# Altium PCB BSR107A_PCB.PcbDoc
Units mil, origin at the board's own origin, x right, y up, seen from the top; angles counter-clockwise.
Board outline 2500 x 2500 mil, 4 copper layers (Top Layer, Signal Layer 1, Signal Layer 2, Bottom Layer), stack 64.4 mil thick; 58 components, 15 nets, 89 pads, 265 vias.
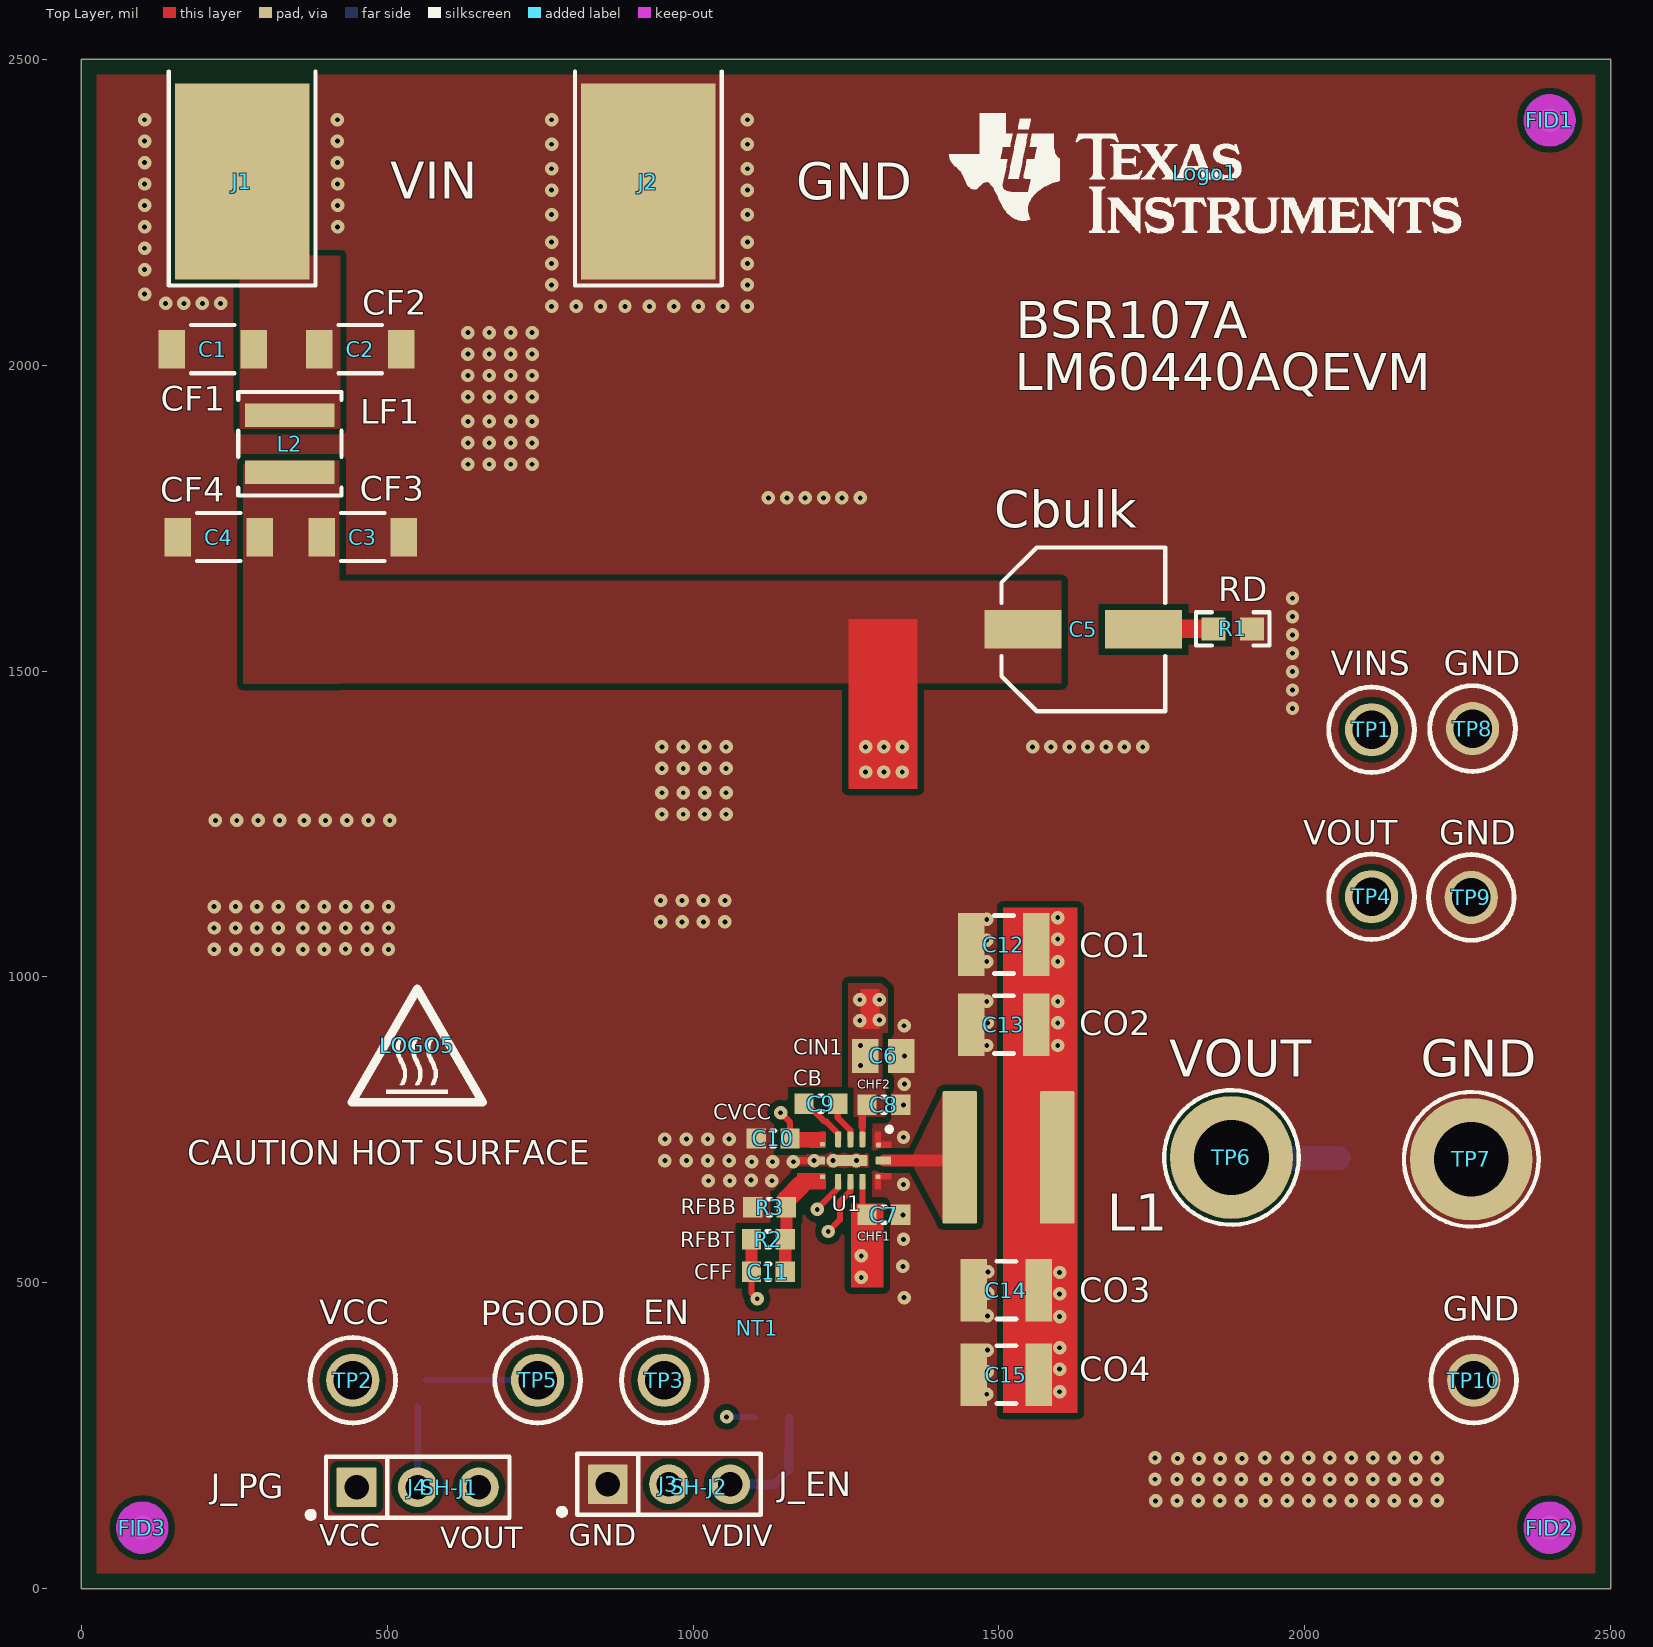
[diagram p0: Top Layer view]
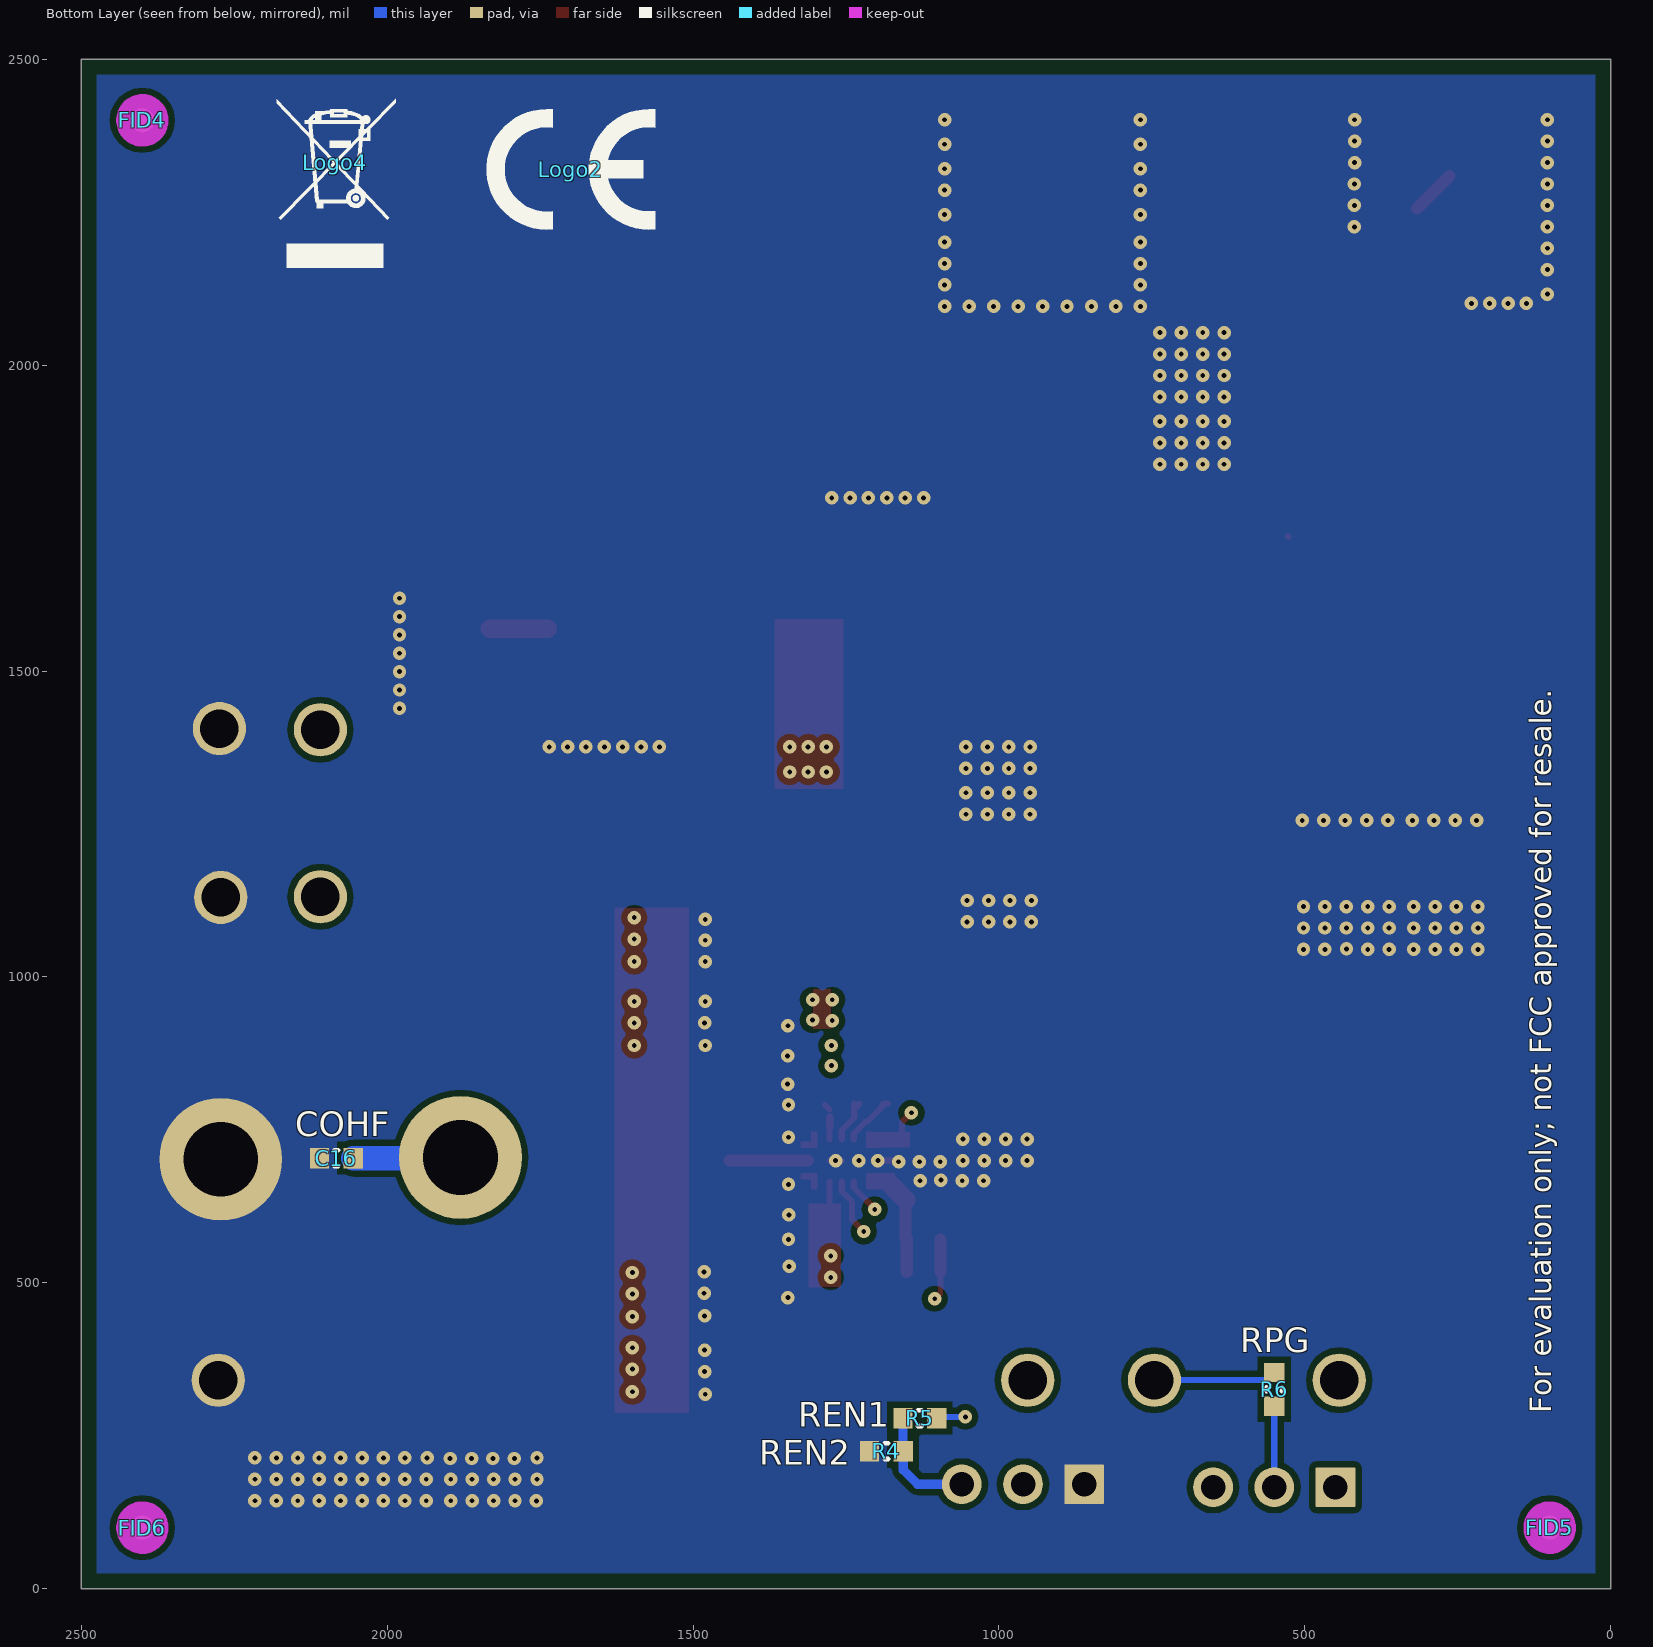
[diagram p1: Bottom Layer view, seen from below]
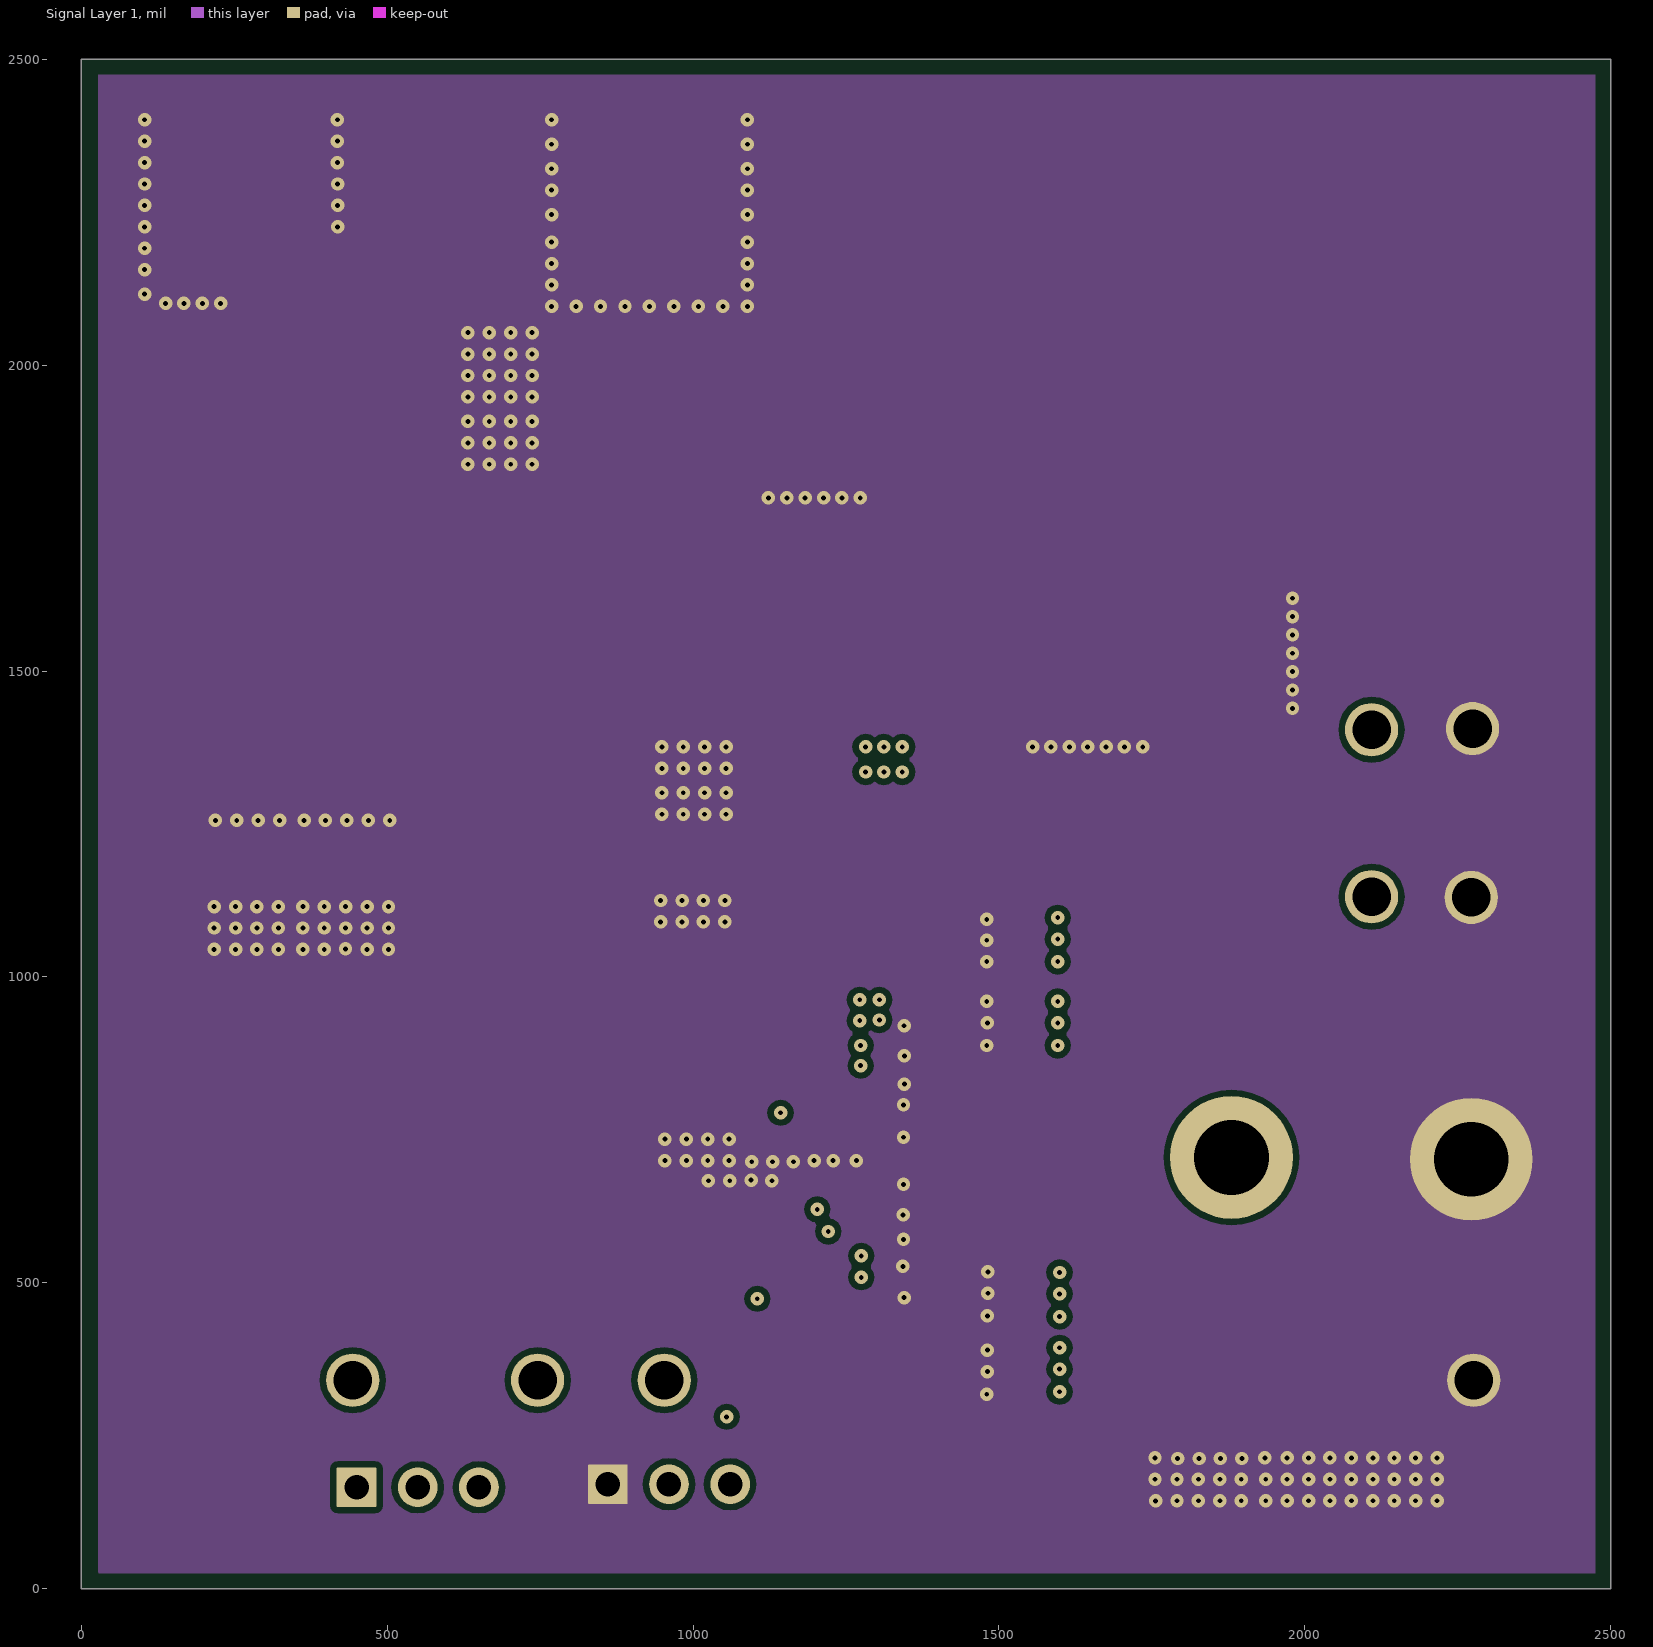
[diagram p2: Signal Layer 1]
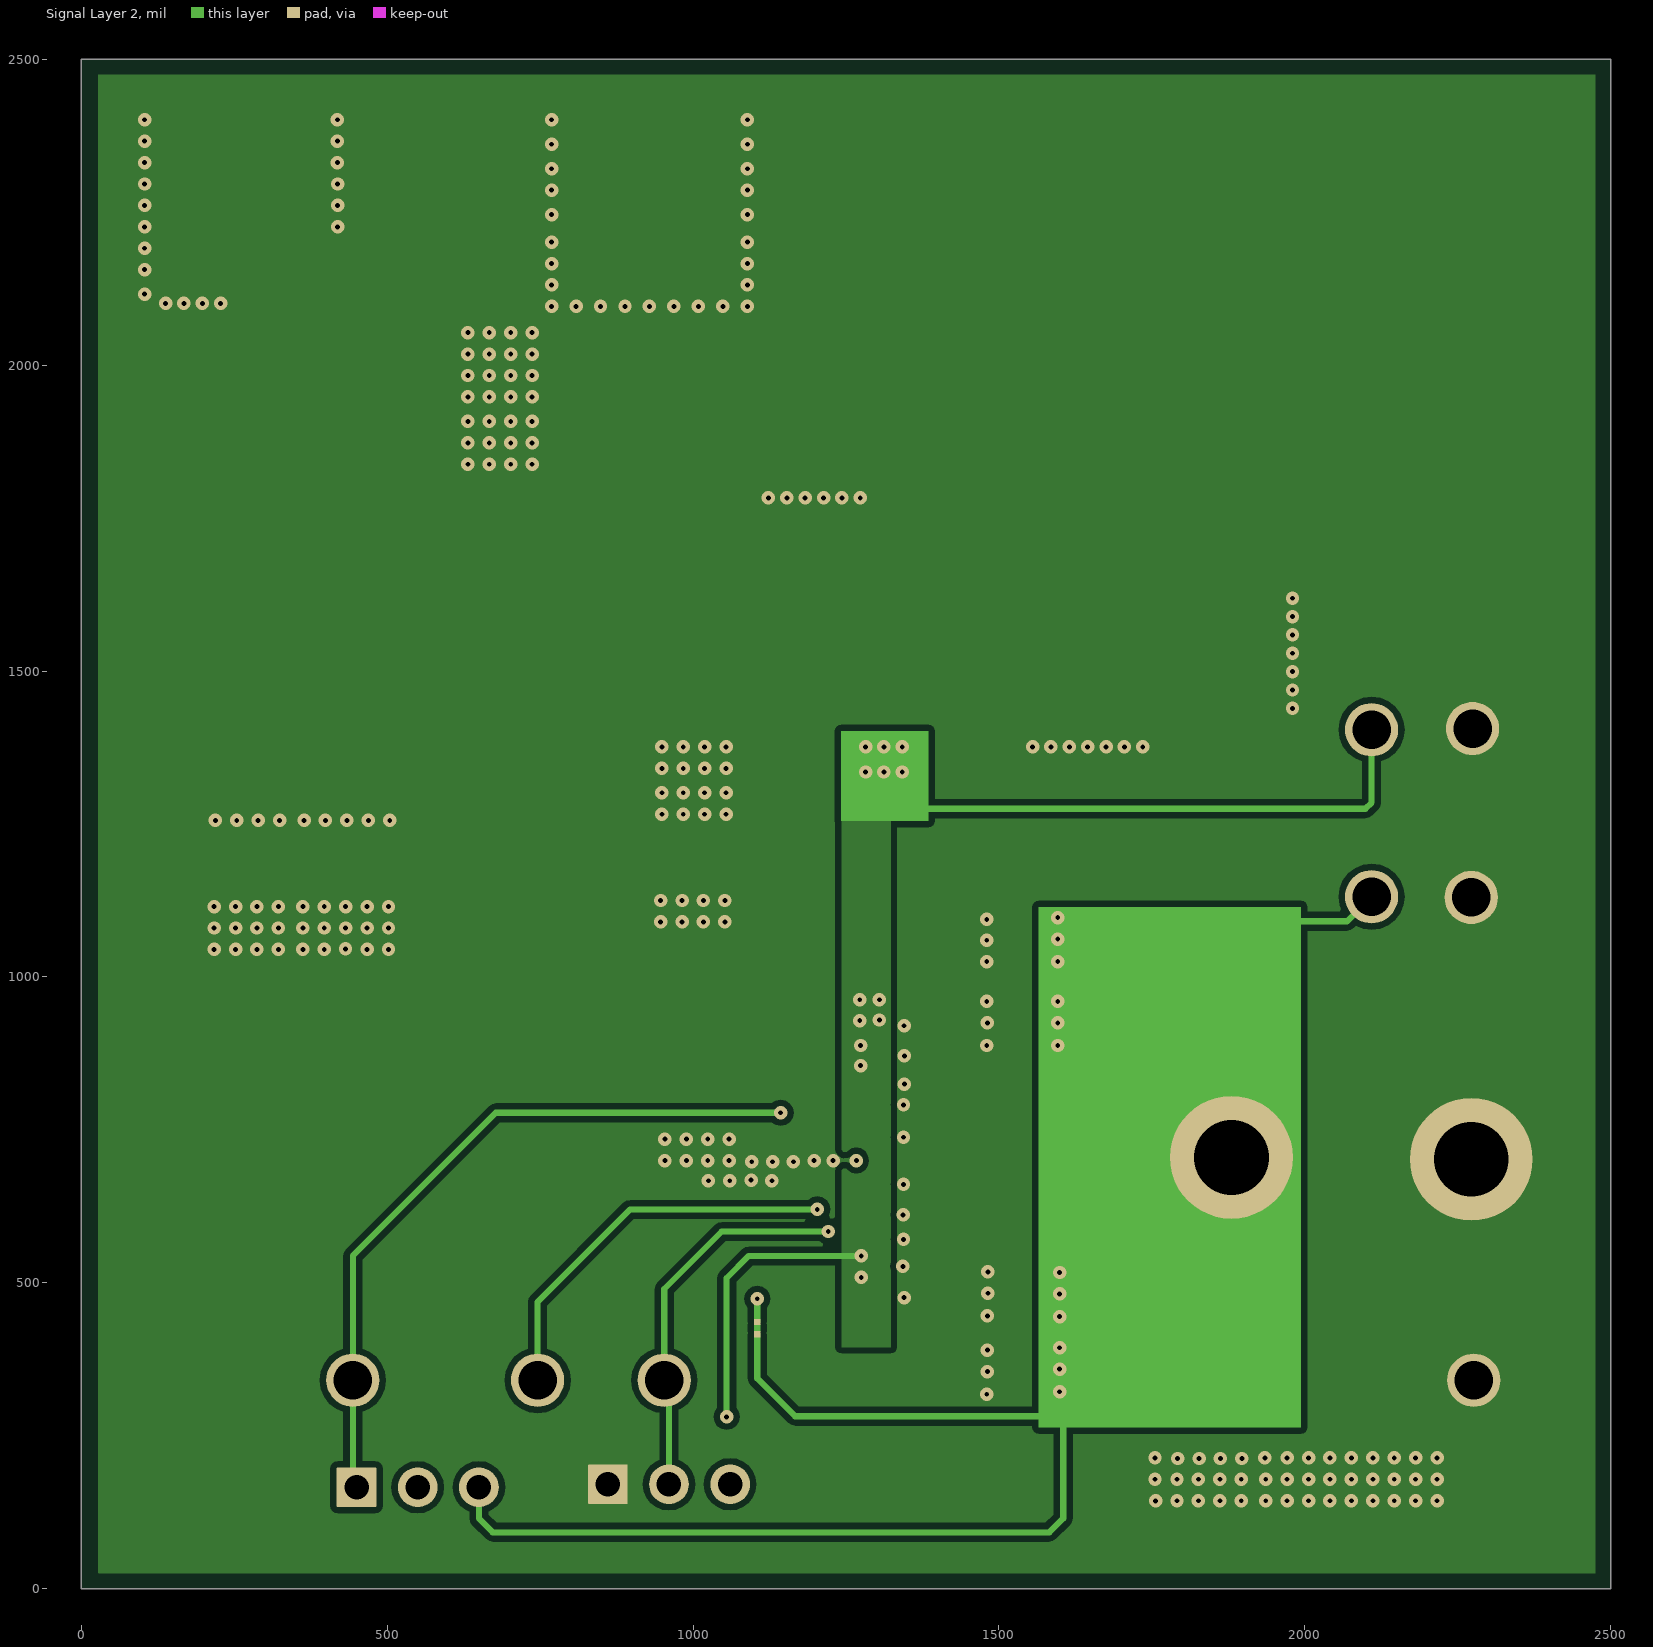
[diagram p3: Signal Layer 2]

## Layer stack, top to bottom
Top Solder: solder mask 0.4, Solder Resist, Dk 3.5
Top Layer: signal copper 2.8
Dielectric 3: core 14, FR-4 High TG, Dk 4.2
Signal Layer 1: signal copper 1.4
Dielectric 2: core 28, FR-4 High TG, Dk 4.2
Signal Layer 2: signal copper 1.4
Dielectric1: core 14, FR-4 HIgh TG, Dk 4.2
Bottom Layer: signal copper 2.8
Bottom Solder: solder mask 0.4, Solder Resist, Dk 3.5

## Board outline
0,0 0,2500 2500,2500 2500,0

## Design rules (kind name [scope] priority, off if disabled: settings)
AcuteAngle [All] p1: minimum=4.50000000000000E+0001 checktracksonly=FALSE
AssemblyTestPointUsage [All] p1: valid=2
BoardOutlineClearance BoardOutlineClearance_MountingHoles [OnCopper and InComponentClass('Mounting Holes')] p1: gap=40 ignorepadtopadclearanceinfootprint=FALSE
BoardOutlineClearance BoardOutlineClearance_Poly [OnCopper and IsPoly] p2: gap=25 ignorepadtopadclearanceinfootprint=FALSE
BoardOutlineClearance [OnCopper and Not InComponentClass('Logo') and not InComponentClass('FiducialMark') and not InRegion(1000,500,4000,800) and not InPoly] p3: gap=40 ignorepadtopadclearanceinfootprint=FALSE
Clearance Clearance_Keepouts [((IsTrack Or IsArc) And Not InPoly) And IsFree and IsKeepOut vs ((IsTrack Or IsArc) And Not InPoly) And IsFree and IsKeepOut] p1: gap=0 ignorepadtopadclearanceinfootprint=FALSE
Clearance Clearance_Poly [InPolygon] p2: gap=10 ignorepadtopadclearanceinfootprint=FALSE except(0: Arc-Hole Track-Hole SMDPad-Hole THPad-Hole Via-Hole Fill-Hole Poly-Hole Region-Hole Text-Hole)
Clearance Clearance_FiducialMark [IsKeepOut and InComponentClass('FiducialMark') vs IsPad and InComponentClass('FiducialMark')] p3: gap=0 ignorepadtopadclearanceinfootprint=FALSE
Clearance [All] p4: gap=7.79 ignorepadtopadclearanceinfootprint=FALSE
ComponentClearance ComponentClearance_MountingHoles_FiducialMarks [InComponentClass('Mounting Holes') vs InComponentClass('FiducialMark')] p1: gap=50 collisioncheckmode=3 verticalgap=10 showdistances=FALSE
ComponentClearance ComponentClearance_Shunt [InComponentClass('Header') vs InComponentClass('Shunt')] p2: gap=0 collisioncheckmode=3 verticalgap=0 showdistances=FALSE
ComponentClearance ComponentClearance_Logo [InComponentClass('Logo')] p3: gap=50 collisioncheckmode=3 verticalgap=10 showdistances=FALSE
ComponentClearance ComponentClearance_ScrewToNut [(HasFootprint('NY PMS 440 0025 PH')) vs (HasFootprint('Keystone_1902C'))] p4: gap=5 collisioncheckmode=3 verticalgap=10 showdistances=FALSE
ComponentClearance ComponentClearance_MountingHoles [InComponentClass('Mounting Holes')] p5: gap=250 collisioncheckmode=3 verticalgap=100000 showdistances=FALSE
ComponentClearance ComponentClearance_SmallPassives [HasFootprint('0201*') or HasFootprint('0402*') or HasFootprint('0508') or HasFootprint('0603*') or HasFootprint('0612') or HasFootprint('0805*') or HasFootprint('0815*') or HasFootprint('0830*') or HasFootprint('1206*') or HasFootprint('1210*') or HasFootprint('1808*') or HasFootprint('1812*') or HasFootprint('1825*') or HasFootprint('2010*') or HasFootprint('2220*') or HasFootprint('2225*') or HasFootprint('2512*') or HasFootprint('2728*') or HasFootprint('3518*') vs HasFootprint('0201*') or HasFootprint('0402*') or HasFootprint('0508') or HasFootprint('0603*') or HasFootprint('0612') or HasFootprint('0805*') or HasFootprint('0815*') or HasFootprint('0830*') or HasFootprint('1206*') or HasFootprint('1210*') or HasFootprint('1808*') or HasFootprint('1812*') or HasFootprint('1825*') or HasFootprint('2010*') or HasFootprint('2220*') or HasFootprint('2225*') or HasFootprint('2512*') or HasFootprint('2728*') or HasFootprint('3518*')] p6: gap=14.96 collisioncheckmode=3 verticalgap=10 showdistances=FALSE
ComponentClearance ComponentClearance_THtoSMT [IsThruComponent vs IsSMTComponent] p7: gap=40 collisioncheckmode=3 verticalgap=30 showdistances=FALSE
ComponentClearance ComponentClearance_THtoTH [IsThruComponent vs IsThruComponent] p8: gap=30 collisioncheckmode=3 verticalgap=30 showdistances=FALSE
ComponentClearance [All] p9: gap=30 collisioncheckmode=3 verticalgap=10 showdistances=FALSE
DiffPairsRouting [All] p1: maxlimit=100 minlimit=10 mostfreqgap=10 toplayer_minwidth=15 toplayer_maxwidth=15 toplayer_prefwidth=15 midlayer1_minwidth=15 midlayer1_maxwidth=15 midlayer1_prefwidth=15 midlayer2_minwidth=15 midlayer2_maxwidth=15 midlayer2_prefwidth=15 bottomlayer_minwidth=15 bottomlayer_maxwidth=15 bottomlayer_prefwidth=15 maxuncoupledlength=1000
FabricationTestPointUsage TestPointUsage [All] p1: valid=2 allowmultiple=FALSE
FabricationTestpoint Testpoint [All] p1: side=3 testpointundercomponent=TRUE minsize=40 maxsize=100 preferedsize=60 minholesize=0 maxholesize=40 preferedholesize=32 testpointgrid=1 allowsidetop=TRUE allowsidebottom=TRUE usegrid=TRUE gridtolerance=0.01
FanoutControl Fanout_LCC [IsLCC] p1: bgadir=Out bgaviamode=Centered fanoutstyle=Auto fanoutdirection=Alternating viagrid=1 // Fanout_LCC (Default Rule)
FanoutControl Fanout_BGA [IsBGA] p2: bgadir=Out bgaviamode=Centered fanoutstyle=Auto fanoutdirection=Alternating viagrid=1 // Fanout_BGA (Default Rule)
FanoutControl Fanout_Default [All] p4: bgadir=Out bgaviamode=Centered fanoutstyle=Auto fanoutdirection=Alternating viagrid=1 // Fanout_Default (Default Rule)
FanoutControl Fanout_Small [(CompPinCount < 5)] p5: bgadir=Out bgaviamode=Centered fanoutstyle=Auto fanoutdirection=OutThenIn viagrid=1 // Fanout_Small (Default Rule)
HoleSize [All] p1: absolutevalues=TRUE maxlimit=251 minlimit=7.87 maxpercent=80.000 minpercent=20.000
MinimumAnnularRing MinimumAnnularRing_ThermalPadVias [IsVia and InAnyComponent] p1: minimumring=5.91
MinimumAnnularRing [All] p2: minimumring=5
MinimumSolderMaskSliver MinimumSolderMaskSliver_Logo [InComponentClass('Logo') vs InComponentClass('Logo')] p1: minsoldermaskwidth=0.7
MinimumSolderMaskSliver [All] p2: minsoldermaskwidth=3.94
PlaneConnect [All] p1: planeconnectstyle=Relief reliefexpansion=10 reliefentries=4 reliefconductorwidth=10 reliefairgap=10
PolygonConnect [All] p1: connectstyle=Direct reliefconductorwidth=10 reliefentries=4 polygonreliefangle="90 Angle" airgapwidth=10
RoutingVias ThermalPadVias [IsVia and InAnyComponent] p1: holewidth=7.87 width=19.68 viastyle="Through Hole" minholewidth=7.87 minwidth=19.68 maxholewidth=12.99 maxwidth=23.62
RoutingVias [All] p2: holewidth=16 width=34 viastyle="Through Hole" minholewidth=7.87 minwidth=18 maxholewidth=40 maxwidth=65
SilkToBoardRegionClearance [Not ((IsComment or IsDesignator) And (Hide <> 'False')) and not InRegion(1000,500,4000,800)] p1:
SilkToSilkClearance SilkToSilkClearance_Pb-FreeLogo [(HasFootprint('Pb-Free_Overlay_Medium') OR HasFootprint('Pb-Free_Overlay_Small')) vs (HasFootprint('Pb-Free_Overlay_Medium') OR HasFootprint('Pb-Free_Overlay_Small'))] p1: silktosilkclearance=0
SilkToSilkClearance [All] p2: silktosilkclearance=4
SilkToSolderMaskClearance SilkToComponentPadClearance [(IsPad or IsFill or IsRegion) and InAnycomponent] p1: minsilkscreentomaskgap=5 clearancetoexposedcopper=TRUE
SilkToSolderMaskClearance "Silk to Solder Mask Opening" [All] p2: minsilkscreentomaskgap=4 clearancetoexposedcopper=FALSE
SolderMaskExpansion [All] p1: expansion=1.97
Width [All] p1: maxlimit=100 minlimit=6 preferedwidth=10 checkconnectedcopper=TRUE
15 further rules are at their usual default settings.

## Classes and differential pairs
component class FiducialMark: FID1 FID2 FID3 FID4 FID5 FID6
component class Shunt: SH-J1 SH-J2
component class Header: J3 J4
component class BSR107A_EVM: 3 C1 C2 C3 C4 C5 C6 C7 C8 C9 C10 C11 C12 C13 C14 C15 C16 CB CHF2 CIN1 COUT1 GND GND4 GND5 J1 J2 J3 J4 L1 L2 NT1 R1 R2 R3 R4 R5 R6 TP1 TP2 TP3 TP4 TP5 TP6 TP7 TP8 TP9 TP10 U1 vin
component class AssemblyNote: ZZ2 ZZ3 ZZ4 ZZ5 ZZ6
component class BSR107A_EVM_Hardware: FID1 FID2 FID3 FID4 FID5 FID6 Logo1 Logo2 Logo3 Logo4 LOGO5 SH-J1 SH-J2 ZZ2 ZZ3 ZZ4 ZZ5 ZZ6
component class Logo: Logo1

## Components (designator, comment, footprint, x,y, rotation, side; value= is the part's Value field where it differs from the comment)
C1 "CF1" 1206_180 215,2026 r180 top value=4.7uF
C2 "CF2" 1206_180 456,2026 r0 top value=4.7uF
C3 "CF3" 1206_180 460,1719 r0 top value=4.7uF
C4 "CF4" 1206_180 225,1719 r180 top value=4.7uF
C5 "Cbulk" SM_RADIAL_D 1638,1568 r0 top value=22uF
C6 "CIN1" 0805L 1311,871 r0 top value=4.7uF
C7 "CHF1" 0603L 1312,611 r0 top value=0.22uF
C8 "CHF2" 0603L 1312,791 r0 top value=0.22uF
C9 "CB" 0603L 1209,793 r180 top value=0.1uF
C10 "CVCC" 0603L 1131,736 r180 top value=1uF
C11 "CFF" 0603L 1123,518 r0 top value=22pF
C12 "CO1" 1210L 1508,1053 r180 top value=22uF
C13 "CO2" 1210_270L 1508,922 r180 top value=47uF
C14 "CO3" 1210_270L 1512,488 r180 top value=47uF
C15 "CO4" 1210L 1512,350 r180 top value=22uF
C16 "COHF" 0603L 2083,704 r0 bottom value=0.1uF
FID1 "Fiducial" Fiducial10-20 2400,2400 r0 top
FID2 "Fiducial" Fiducial10-20 2400,100 r0 top
FID3 "Fiducial" Fiducial10-20 100,100 r0 top
FID4 "Fiducial" Fiducial10-20 2400,2400 r180 bottom
FID5 "Fiducial" Fiducial10-20 100,100 r180 bottom
FID6 "Fiducial" Fiducial10-20 2400,100 r180 bottom
J1 "VIN" 6091 263,2485 r270 top
J2 "GND" 6092 927,2485 r270 top
J3 "J_EN" Samtec_HTSW-103-07-G-S 960.67,170.89 r0 top
J4 "J_PG" Samtec_HTSW-103-07-G-S 550,166 r0 top
L1 "XAL6060-682MEB" XAL6060 1515.5,705 r0 top value=6.8uH
L2 "LF1" XAL4030 341,1871.5 r270 top value=3.3uH
Logo1 "Texas Instruments" TI_Stacked_Overlay_Small 1836.89,2313.76 r0 top
Logo2 "CE Mark" CE_Mark_5mm 1699.85,2319.94 r180 bottom
Logo3 "FCC disclaimer" FCC_disclaimer -478.56,846.5 r180 bottom
Logo4 "WEEE logo" WEEE_Minimum 2085.16,2331 r180 bottom
LOGO5 "CAUTION HOT SURFACE" IEC_HotSurface_Small 549,888 r0 top
NT1 "Net-Tie" Net-Tie_10mil 1105,426 r270 top net-tie
R1 "RD" 0603 1882,1569 r180 top value=0
R2 "RFBT" 0603L 1123,571 r180 top value=100k
R3 "RFBB" 0603L 1125,624 r0 top value=24.9k
R4 "REN2" 0603L 1184,225 r180 bottom value=10.0k
R5 "REN1" 0603L 1129.35,279 r180 bottom value=10.0k
R6 "RPG" 0603L 550,326 r90 bottom value=100k
SH-J1 "SNT-100-BK-G" SNT-100-BK-G 602,166 r180 top value=1x2
SH-J2 "SNT-100-BK-G" SNT-100-BK-G 1010,167 r180 top value=1x2
TP1 "VINS" Keystone5010 2109,1404 r0 top
TP2 "VCC" Keystone5014 444,341 r0 top
TP3 "EN" Keystone5014 953,341 r0 top
TP4 "VOUT" Keystone5010 2109,1131 r0 top
TP5 "PGOOD" Keystone5014 746,341 r0 top
TP6 "VOUT" Keystone1503-2 1880,705 r0 top
TP7 "GND" Keystone1503-2 2272,702 r0 top
TP8 "GND" Keystone5011 2274,1406 r0 top
TP9 "GND" Keystone5011 2272,1130 r0 top
TP10 "GND" Keystone5011 2276,341 r0 top
U1 "LM60440-Q1" RPK0013A 1257,700 r270 top
ZZ2 "These assemblies are ESD sensitive, ESD precautions shall be observed." AssemblyNote 52.27,3634.11 r0 top
ZZ3 "These assemblies must be clean and free from flux and all contaminants. Use of no clean flux is not acceptable." AssemblyNote 52.27,3545.56 r0 top
ZZ4 "These assemblies must comply with workmanship standards IPC-A-610 Class 2, unless otherwise specified." AssemblyNote 52.27,3457 r0 top
ZZ5 "Place shunt jumper (SH-J1) on jumper (J3) in position 2-3" AssemblyNote 50,3269.73 r0 top
ZZ6 "Place shunt jumper (SH-J2) on jumper (J4) in position 2-3" AssemblyNote 51,3362.73 r0 top

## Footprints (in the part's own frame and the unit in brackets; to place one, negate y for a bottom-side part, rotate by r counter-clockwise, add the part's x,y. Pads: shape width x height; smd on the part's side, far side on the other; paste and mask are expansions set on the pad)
0603 [mm] "0603 from SM-752 data"
  rect 1x0.95 smd: 1(-0.8,0) 2(0.8,0)
  silkscreen extent -1.52,-0.69 1.52,0.69, body extent -0.87,-0.47 0.87,0.47, height 1
0603L [mm] "0603 from SM-752 data"
  rect 0.8x0.85 smd: 1(-0.7,0) 2(0.7,0)
  silkscreen extent -0.07,-0.33 0.07,0.33, body extent -0.87,-0.47 0.87,0.47, height 1
0805L [mm] "0805 from SM-752 data"
  rect 1.1x1.4 smd: 1(-0.75,0) 2(0.75,0)
  body extent -1.1,-0.72 1.1,0.72, height 1.45
1206_180 [mm] "1206_180"
  rect 1.1x1.6 smd: 1(-1.7,0) 2(1.7,0)
  silkscreen extent -0.9,-1 0.9,1, body extent -1.75,-0.95 1.75,0.95, height 1.8
1210_270L [mm] "1210"
  rect 1.1x2.6 smd: 1(-1.35,0) 2(1.35,0)
  silkscreen extent -0.4,-1.2 0.4,1.2, body extent -1.7,-1.35 1.7,1.35, height 2.7
1210L [mm] "1210 from SM-752 data"
  rect 1.1x2.6 smd: 1(-1.35,0) 2(1.35,0)
  silkscreen extent -0.4,-1.2 0.4,1.2, body extent -1.7,-1.35 1.7,1.35, height 1.35
6091 [mil] "Keystone Insulated End Launch Banana Jack"
  rect 320x220 smd: 1(185,0)
  silkscreen extent 5,-120 355,120, body extent -666,-216 271,216, height 227
6092 [mil] "Keystone Insulated End Launch Banana Jack"
  rect 320x220 smd: 1(185,0)
  silkscreen extent 5,-120 355,120, body extent -666,-216 271,216, height 227
AssemblyNote [mil] "Assembly Note"
CE_Mark_5mm [mil] "Minimum text height for CE Mark"
  silkscreen extent -138,-98 138,98
FCC_disclaimer [mil]
Fiducial10-20 [mm]
  round 1 smd mask+0.5: 1(0,0)
  Top Layer keep-out circle w1.178: c0,0 r0.5
IEC_HotSurface_Small [mil]
  silkscreen extent -107,-93 107,92
Keystone1503-2 [mm] "Double Turret"
  round 5.1 hole 3.1: 1(0,0)
  silkscreen extent -2.79,-2.79 2.79,2.79, body extent -2.4,-2.4 2.38,2.4, height 9.22
Keystone5010 [mil] "Keystone Multipurpose loops"
  round 87 hole 63: 1(0,0)
  silkscreen extent -70,-70 70,70, body extent -63,-63 63,62, height 319
Keystone5011 [mil] "Keystone Multipurpose loops"
  round 87 hole 63: 1(0,0)
  silkscreen extent -70,-70 70,70, body extent -63,-63 63,62, height 319
Keystone5014 [mil] "Keystone Multipurpose loops"
  round 87 hole 63: 1(0,0)
  silkscreen extent -70,-70 70,70, body extent -63,-63 63,62, height 319
Net-Tie_10mil [mil] "10mil net tie, no solder mask opening, no solder paste"
  rect 10x10 on Mid2 paste-5 mask-5: 1(-10,0) 2(10,0)
  Signal Layer 2 region: -6,5 6,5 6,-5 -6,-5
RPK0013A [mm] "QFN, 13-Leads, Body 2x3mm, Ptich 0.5mm"
  rrect50% 0.2x0.2 smd: 1(-0.65,1.175) 5(-0.675,-1.15) 7(0.675,-1.15) 11(0.675,1.15)
  rrect40% 0.65x0.25 smd: 2(-0.875,0.5) 3(-0.875,0) 4(-0.875,-0.5) 8(0.875,-0.5) 9(0.875,0) 10(0.875,0.5)
  rrect29% 0.35x0.65 smd: 6(0,-1.375) 12(0,1.375)
  rrect22% 0.45x1.45 smd: 13(0,0)
  Top Layer region: -1.2,1.075 -1.2,1.225 -1.196,1.244 -1.185,1.26 -1.169,1.271 -1.15,1.275 -1.15,1.275 -0.825,1.275 -0.806,1.279 -0.79,1.29 -0.779,1.306 -0.775,1.325 -0.775,1.325 -0.775,1.65 -0.771,1.669 -0.76,1.685 -0.744,1.696 -0.725,1.7 -0.725,1.7 -0.575,1.7 -0.556,1.696 -0.54,1.685 -0.529,1.669 -0.525,1.65 -0.525,1.65 -0.525,1.075 -0.529,1.056 -0.54,1.04 -0.556,1.029 -0.575,1.025 -0.575,1.025 -1.15,1.025 -1.169,1.029 -1.185,1.04 -1.196,1.056 -1.2,1.075
  Top Layer region: 1.2,1.075 1.2,1.225 1.196,1.244 1.185,1.26 1.169,1.271 1.15,1.275 1.15,1.275 0.825,1.275 0.806,1.279 0.79,1.29 0.779,1.306 0.775,1.325 0.775,1.325 0.775,1.65 0.771,1.669 0.76,1.685 0.744,1.696 0.725,1.7 0.725,1.7 0.575,1.7 0.556,1.696 0.54,1.685 0.529,1.669 0.525,1.65 0.525,1.65 0.525,1.075 0.529,1.056 0.54,1.04 0.556,1.029 0.575,1.025 0.575,1.025 1.15,1.025 1.169,1.029 1.185,1.04 1.196,1.056 1.2,1.075
  Top Layer region: 0.575,-1.7 0.725,-1.7 0.744,-1.696 0.76,-1.685 0.771,-1.669 0.775,-1.65 0.775,-1.65 0.775,-1.325 0.779,-1.306 0.79,-1.29 0.806,-1.279 0.825,-1.275 0.825,-1.275 1.15,-1.275 1.169,-1.271 1.185,-1.26 1.196,-1.244 1.2,-1.225 1.2,-1.225 1.2,-1.075 1.196,-1.056 1.185,-1.04 1.169,-1.029 1.15,-1.025 1.15,-1.025 0.575,-1.025 0.556,-1.029 0.54,-1.04 0.529,-1.056 0.525,-1.075 0.525,-1.075 0.525,-1.65 0.529,-1.669 0.54,-1.685 0.556,-1.696 0.575,-1.7
  Top Layer region: -0.575,-1.7 -0.725,-1.7 -0.744,-1.696 -0.76,-1.685 -0.771,-1.669 -0.775,-1.65 -0.775,-1.65 -0.775,-1.325 -0.779,-1.306 -0.79,-1.29 -0.806,-1.279 -0.825,-1.275 -0.825,-1.275 -1.15,-1.275 -1.169,-1.271 -1.185,-1.26 -1.196,-1.244 -1.2,-1.225 -1.2,-1.225 -1.2,-1.075 -1.196,-1.056 -1.185,-1.04 -1.169,-1.029 -1.15,-1.025 -1.15,-1.025 -0.575,-1.025 -0.556,-1.029 -0.54,-1.04 -0.529,-1.056 -0.525,-1.075 -0.525,-1.075 -0.525,-1.65 -0.529,-1.669 -0.54,-1.685 -0.556,-1.696 -0.575,-1.7
  body extent -1,-1.5 1,1.5, height 0.65
Samtec_HTSW-103-07-G-S [mm] "Samtec 100mil, 1x3, 230 mil above insulator"
  rrect6% 1.65x1.65 hole 1.016: 1(-2.54,0)
  round 1.65 hole 1.016: 2(0,0) 3(2.54,0)
  silkscreen extent -4.57,-1.27 3.81,1.27, body extent -3.81,-1.27 3.81,1.27, height 8.38
SM_RADIAL_D [mm] "6.3 x 5.8mm:  Panasonic D"
  rect 3.2x1.6 smd: 1(-2.5,0) 2(2.5,0)
  silkscreen extent -3.4,-3.4 3.4,3.4, body extent -3.4,-3.4 3.4,3.4, height 6.1
SNT-100-BK-G [mil] "Samtec STEP model"
  round 1 on Mech3: 0(0,0)
  body extent -100,-50 100,50, height 344
TI_Stacked_Overlay_Small [mil]
  silkscreen extent -418,-98 418,98
WEEE_Minimum [mil] "WEEElie bin"
  silkscreen extent -95,-172 99,104
XAL4030 [mil] "Coilcraft XAL4030 7/18/12"
  rect 38x146 smd: 1(-46.5,0) 2(46.5,0)
  silkscreen extent -85,-85 85,85, body extent -84,-84 84,84, height 122
XAL6060 [mm] "Coilcraft recommended land pattern Document 887-4 Revised 01/14/18"
  rrect7% 1.43x5.5 smd: 1(-2.019,0) 2(2.019,0)
  body extent -3.28,-3.38 3.28,3.38, height 6.11

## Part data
C1 C2 C3 C4: library part CMP-0008969-2, "CAP, CERM, 4.7 uF, 50 V, +/- 10%, X7R, 1206", Cap_Case=2220, Manufacturer=MuRata, PartNumber=GRM31CR71H475KA12L, Supplier Part Number 1=24R6347, TempCo=X7R, Tolerance_%=10%, Value1=Unknown, Value2=50V, ValueDisplayed=4.7uF
C5: library part CMP-0011179-2, "CAP, AL, 22 uF, 50 V, +/- 20%, 0.88 ohm, AEC-Q200 Grade 2, SMD", Cap_Case=D, Manufacturer=Panasonic, PartNumber=EEE-FK1H220P, Supplier Part Number 1=PCE3811CT-ND, Tolerance_%=20%, Value1="0.88 ohm", Value2=50V, ValueDisplayed=22uF
C6: library part CMP-0007840-2, "CAP, CERM, 4.7 uF, 50 V, +/- 10%, X5R, 0805", Cap_Case=0805, Manufacturer=TDK, PartNumber=C2012X5R1H475K125AB, Supplier Part Number 1=445-5980-1-ND, TempCo=X5R, Tolerance_%=10%, Value1="0.002346 ohm", Value2=50V, ValueDisplayed=4.7uF
C7 C8: library part CMP-0007047-4, "CAP, CERM, 0.22 uF, 50 V, +/- 10%, X7R, 0603", Cap_Case=0603, Manufacturer=TDK, PartNumber=C1608X7R1H224K080AB, Supplier Part Number 1=445-7408-1-ND, TempCo=X7R, Tolerance_%=10%, Value1="0.021699 ohm", Value2=50V, ValueDisplayed=0.22uF
C9 C16: library part CMP-0006753-4, "CAP, CERM, 0.1 uF, 25 V, +/- 10%, X7R, 0603", Cap_Case=0603, Manufacturer=AVX, PartNumber=06033C104KAT2A, Supplier Part Number 1=478-3714-1-ND, TempCo=X7R, Tolerance_%=10%, Value1="0.05 ohm", Value2=25V, ValueDisplayed=0.1uF
C10: library part CMP-0006833-4, "CAP, CERM, 1 uF, 25 V, +/- 10%, X7R, 0603", Cap_Case=0603, Manufacturer="Wurth Elektronik", PartNumber=885012206076, Supplier Part Number 1=732-7994-1-ND, TempCo=X7R, Tolerance_%=10%, Value1=Unknown, Value2=25V, ValueDisplayed=1uF
C11: library part CMP-0007196-2, "CAP, CERM, 22 pF, 50 V, +/- 5%, C0G/NP0, 0603", Cap_Case=0603, Manufacturer=MuRata, PartNumber=GRM1885C1H220JA01D, Supplier Part Number 1=490-1411-1-ND, TempCo=C0G/NP0, Tolerance_%=5%, Value1=Unknown, Value2=50V, ValueDisplayed=22pF
C12 C15: library part CMP-0009169-2, "CAP, CERM, 22 uF, 25 V, +/- 10%, X5R, 1210", Cap_Case=1210, Manufacturer="Samsung Electro-Mechanics", PartNumber=CL32A226KAJNNNE, TempCo=X5R, Tolerance_%=10%, Value1=Unknown, Value2=25V, ValueDisplayed=22uF
C13 C14: library part CMP-0009211-2, "CAP, CERM, 47 uF, 16 V, +/- 10%, X5R, 1210", Cap_Case=1210, Manufacturer=MuRata, PartNumber=GRM32ER61C476KE15L, Supplier Part Number 1=GRM32ER61C476KE15L-ND, TempCo=X5R, Tolerance_%=10%, Value1=Unknown, Value2=16V, ValueDisplayed=47uF
FID1 FID2 FID3 FID4 FID5 FID6: library part CMP-0077181-1, "Fiducial mark.  There is nothing to buy or mount.", Manufacturer=N/A
J1: library part CMP-0055167-2, "Standard Banana Jack, Insulated, Red", Manufacturer=Keystone, PartNumber=6091, Supplier Part Number 1=36-6091-ND
J2: library part CMP-0055168-2, "Standard Banana Jack, Insulated, Black", Manufacturer=Keystone, PartNumber=6092, Supplier Part Number 1=36-6092-ND
J3 J4: library part CMP-0075484-1, "Header, 100mil, 3x1, Gold, TH", Manufacturer=Samtec, PartNumber=HTSW-103-07-G-S, Supplier Part Number 1=HTSW-103-07-G-S-ND
L1: library part CMP-0061022-2, "Inductor, Shielded, Composite, 6.8 µH, 9 A, 0.0208 ohm, AEC-Q200 Grade 1, SMD", Manufacturer=Coilcraft, Value1="0.0208 ohm", Value2=9.2A, ValueDisplayed=6.8uH
L2: library part CMP-0060989-1, "Inductor, Shielded, Composite, 3.3 uH, 5.5 A, 0.026 ohm, SMD", Manufacturer=Coilcraft, PartNumber=XAL4030-332MEB, Supplier Part Number 1=994-XAL4030-332MEB, Value1="0.026 ohm", Value2=5.5A, ValueDisplayed=3.3uH
Logo1: library part CMP-0074838-1, "Texas Instrument Corporate Signature"
Logo2: library part CMP-0074844-1
Logo3: library part CMP-0074847-1, "FCC_disclaimer"
Logo4: library part CMP-0074769-1
LOGO5: library part CMP-0074837-1, "IEC 61010-1 Hot Surface Warning"
NT1: library part CMP-0078142-2, "Single point connection between nets.", Manufacturer=N/A
R1: library part CMP-0023343-3, "RES, 0, 1%, 0.1 W, AEC-Q200 Grade 0, 0603", Manufacturer="Stackpole Electronics Inc", PartNumber=RMCF0603ZT0R00, Power_W=100mW, Supplier Part Number 1=RMCF0603ZT0R00CT-ND, TempCo=ppm/C, Tolerance_%=1%, Value2=0.1W, Value_Code=0
R2: library part CMP-0022735-5, "RES, 100 k, 1%, 0.1 W, 0603", Manufacturer=Yageo, PartNumber=RC0603FR-07100KL, Power_W=100mW, Supplier Part Number 1=311-100KHRCT-ND, TempCo="100 ppm/C", Tolerance_%=1%, Value2=0.1W, Value_Code=100k
R3: library part CMP-0022237-4, "RES, 24.9 k, 1%, 0.1 W, AEC-Q200 Grade 0, 0603", Manufacturer=Vishay-Dale, PartNumber=CRCW060324K9FKEA, Power_W=100mW, Supplier Part Number 1=541-24.9KHCT-ND, TempCo="100 ppm/C", Tolerance_%=1%, Value2=0.1W, Value_Code=24k9, ValueDisplayed=24.9k
R4 R5: library part CMP-0021998-4, "RES, 10.0 k, 1%, 0.1 W, AEC-Q200 Grade 0, 0603", Manufacturer=Vishay-Dale, PartNumber=CRCW060310K0FKEA, Power_W=100mW, Supplier Part Number 1=541-10.0KHCT-ND, TempCo="100 ppm/C", Tolerance_%=1%, Value2=0.1W, Value_Code=10k0, ValueDisplayed=10.0k
R6: library part CMP-0021990-4, "RES, 100 k, 1%, 0.1 W, AEC-Q200 Grade 0, 0603", Manufacturer=Vishay-Dale, PartNumber=CRCW0603100KFKEA, Power_W=100mW, Supplier Part Number 1=541-100KHCT-ND, TempCo="100 ppm/C", Tolerance_%=1%, Value2=0.1W, Value_Code=100k
SH-J1 SH-J2: library part CMP-0003623-1, "Shunt, 100mil, Gold plated, Black", Alternate Manufacturer=3M, Alternate PartNumber=969102-0000-DA, Manufacturer=Samtec, Supplier Part Number 1=SNT-100-BK-G-ND
TP1 TP4: library part CMP-0055147-1, "Test Point, Multipurpose, Red, TH", Color=Red, Manufacturer=Keystone, PartNumber=5010, Supplier Part Number 1=36-5010-ND
TP2 TP3 TP5: library part CMP-0055151-1, "Test Point, Multipurpose, Yellow, TH", Color=Yellow, Manufacturer=Keystone, PartNumber=5014, Supplier Part Number 1=36-5014-ND
TP6 TP7: library part 1503-2, "Terminal, Turret, TH, Double", Manufacturer=Keystone, Supplier Part Number 1=36-1503-2-ND
TP8 TP9 TP10: library part CMP-0055148-1, "Test Point, Multipurpose, Black, TH", Color=Black, Manufacturer=Keystone, PartNumber=5011, Supplier Part Number 1=36-5011-ND
U1: library part CMP-0085873-1, "LM60440-Q1, RPK0013A (VQFN-12)", Alternate Manufacturer="Texas Instruments", Alternate PartNumber=LM60440AQRPKRQ1
ZZ2: library part CMP-0077236-1
ZZ3: library part CMP-0077237-1
ZZ4: library part CMP-0077238-1
ZZ5 ZZ6: library part CMP-0077238-1, "These assemblies must comply with workmanship standards IPC-A-610 Class 2, unless otherwise specified."

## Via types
v1: diameter 22, hole 8, Top Layer to Bottom Layer, 250 vias
v2: diameter 22, hole 8, Top Layer to Bottom Layer, tented both sides, 13 vias
v3: diameter 22/22/22/22 (per signal layer), hole 8, Top Layer to Bottom Layer, 2 vias

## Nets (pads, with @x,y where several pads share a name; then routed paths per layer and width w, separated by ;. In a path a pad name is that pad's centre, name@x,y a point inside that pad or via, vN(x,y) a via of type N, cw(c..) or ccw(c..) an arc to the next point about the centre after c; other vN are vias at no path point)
BOOT: C9.2 U1.4 | length 91.7
  Top Layer w10: C9.2 C9.2@1185.98,793 ; C9.2@1191.02,790.71 1188.73,793 C9.2@1185.98,793 ; U1.4 1237.31,743.94 1217.78,763.47 1215.51,763.47 C9.2@1185.98,793
EN: J3.2 TP3.1 U1.9 | length 736.5
  Top Layer w10: v1(1221,584) 1240,603 1240,632.58 1257,649.58 U1.9
  Signal Layer 2 w10: J3.2 960.67,333.33 TP3.1 953,490 1047,584 v1(1221,584)
  Bottom Layer w10: J3.2@953,178.56 J3.2
FB: C11.2 R2.1 R3.2 U1.7 | length 174.9
  Top Layer w10: R2.1@1151.56,571 R2.1@1152.56,572 ; R3.2 R3.2@1152.56,635.81 ; 1177.38,660.63 1199,660.63
  Top Layer w20: C11.2 R2.1 ; R2.1@1152.56,572 R3.2
  Top Layer w31.5: R3.2@1152.56,635.81 1177.38,660.63
GND: C1.2 C2.2 C3.2 C4.2 C6.2 C7.2 C8.2 C10.2 C12.2 C13.2 C14.2 C15.2 C16.2 J2.1 J3.1 R1.1 R3.1 R4.1 TP7.1 TP8.1 TP9.1 TP10.1 U1.1 U1.6 U1.11 U1.13 | length 58
  Top Layer w10: C3.2 C3.2@527.93,1720 ; U1.13 U1.13@1276.69,700
  Top Layer w12: v1@1166,700 U1.6
  other v1: 1756,143.73 1791,144 1826,144 1861,144 1896,144 1936,144 1971,144 2006,144 2041,144 2076,144 2111,144 2146,144 2181,144 2216,144 1755,179 1791,179 1826,179 1861,179 1896,179 1936,179 1971,179 2006,179 2041,179 2076,179 2111,179 2146,179 2181,179 2216,179 1792,213 1827,213 1862,213 1897,213 1755,214 1934.73,214 1971,214 2006,214 2041,214 2076,214 2111,214 2146,214 2181,214 2216,214 1345,476 1343,527 1344,571 1343.43,611 1344,661 1025,667 1060,667 1129,667 1095,668 1096,698 1130,698 1164,698 954,700 989,700 1024,700 1059,700 1197.95,699.99 1229,700 1266.84,700 954,735 989,735 1024,735 1059,735 1344,738 1344,791 1345.45,871 1345,920.19 217.27,1045 252.27,1045 287.27,1045 322.27,1045 362.27,1045 397.27,1045 467.27,1045 502.27,1045 432,1046 217.27,1080 252.27,1080 287.27,1080 322.27,1080 362.27,1080 397.27,1080 432.27,1080 467.27,1080 502.27,1080 947,1090 982,1090 1017,1090 1052,1090 217.27,1115 252.27,1115 287.27,1115 322.27,1115 362.27,1115 397.27,1115 432.27,1115 467.27,1115 502.27,1115 947,1125 982,1125 1017,1125 1052,1125 219.27,1256 254.27,1256 289.27,1256 324.27,1256 364.27,1256 399.27,1256 434.27,1256 469.27,1256 504.27,1256 949,1266 984,1266 1019,1266 1054,1266 949,1301 984,1301 1019,1301 1054,1301 949,1341 984,1341 1019,1341 1054,1341 949,1376 984,1376 1019,1376 1054,1376 1555,1376 1585,1376 1615,1376 1645,1376 1675,1376 1705,1376 1735,1376 1979.72,1439 1979.72,1469 1979.72,1499 1979.72,1529 1979.72,1559 1979.72,1589 1979.72,1619 1123.27,1783 1153.27,1783 1183.27,1783 1213.27,1783 1243.27,1783 1273.27,1783 632,1838 667,1838 702,1838 737,1838 632,1873 667,1873 702,1873 737,1873 632,1908 667,1908 702,1908 737,1908 632,1948 667,1948 702,1948 737,1948 632,1983 667,1983 702,1983 737,1983 632,2018 667,2018 702,2018 737,2018 632,2053 667,2053 702,2053 737,2053 768.77,2096 808.77,2096 848.77,2096 888.77,2096 928.77,2096 968.77,2096 1008.77,2096 1048.77,2096 1088.77,2096 138,2101 198,2101 103.77,2116 768.77,2131 1088.77,2131 103.77,2156 768.77,2166 1088.77,2166 103.77,2191 768.77,2201 1088.77,2201 103.77,2226 419,2226 768.77,2246 1088.77,2246 103.77,2261 419,2261 768.77,2286 1088.77,2286 103.77,2296 419,2296 768.77,2321 1088.77,2321 103.77,2331 418.77,2331 768.77,2361 1088.77,2361 103.77,2366 418.77,2366 103.77,2401 418.77,2401 768.77,2401 1088.77,2401
  other v2: 1480,318 1481,355 1481,390 1481,446 1482,483 1482,518 1345.45,825 1480,888 1481,925 1480,960 1480,1025 1480,1060 1480,1094
  other v3: 168,2101 228,2101
NetC5_2: C5.2 R1.2 | length 96.1
  Top Layer w10: C5.2 C5.2@1737.43,1569
  Top Layer w30: C5.2@1737.43,1569 1810.44,1569 R1.2@1832.13,1569
NetJ4_2: J4.2 R6.1 | length 150.8
  Bottom Layer w10: R6.1 J4.2 J4.2@563,179
PGOOD: R6.2 TP5.1 U1.8 | length 890.3
  Top Layer w10: v1(1203,620) 1203,621.17 1237.31,655.48 U1.8
  Signal Layer 2 w10: TP5.1 746,469 897,620 v1(1203,620)
  Bottom Layer w10: R6.2@563,341 TP5.1
SW1: L1.1 U1.12 | length 127.9
  Top Layer w20: U1.12@1312.13,700 L1.1@1440,700
SW2: C9.1 U1.3 | length 72.1
  Top Layer w10: C9.1@1227.7,793 C9.1@1230.64,788.83 ; C9.1 1236.56,769.86 1257,749.42 U1.3
VCC: C10.1 J4.1 TP2.1 U1.5 | length 1224
  Top Layer w10: v1(1143,778) 1158.56,762.44 C10.1
  Signal Layer 2 w10: J4.1@444,166 TP2.1 444,544.43 677.57,778 v1(1143,778) v1@1144,777
VDIV: J3.3 R4.2 R5.1 | length 190.3
  Bottom Layer w10: R4.2 R4.2@1156.91,225.46
  Bottom Layer w15: J3.3 1132.89,170.89 1156.44,194.44 R4.2 ; R4.2@1156.91,225.46 R5.1
VIN: C1.1 C2.1 J1.1 L2.1 | length 75
  Top Layer w20: J1.1@263.77,2309 J1.1@316.77,2256
VINS: C3.1 C4.1 C5.1 C6.1 C7.1 C8.1 L2.2 R5.2 TP1.1 U1.2 U1.10 | length 1492.4
  Top Layer w10: U1.10 1276.68,618.76 C7.1 ; U1.2 1276.68,755.27 ; C8.1@1276.68,783.24 C8.1
  Top Layer w12: 1276.68,755.27 1276.68,771.43
  Signal Layer 2 w10: v1(1055,281) 1055,508 1091,544 v1(1275,544) ; 1355,1275 2099,1275 2109,1285 TP1.1
  Bottom Layer w10: v1(1055,281) 1099.79,281 R5.2
  other v1: 1275,509 1274,855 1274,888 1272.44,928.68 1304.44,929.68 1272.44,962.68 1304.44,962.68 1282,1335 1312,1335 1342,1335 1282,1376 1312,1376 1342,1376
VOS: C11.1 NT1.1 R2.2 | length 141
  Top Layer w10: R2.2@1094,569.56 R2.2 ; C11.1 1095.44,483.56 v1(1105,474)
  Top Layer w20: C11.1 R2.2
  Signal Layer 2 w10: NT1.1 v1(1105,474)
VOUT: C12.1 C13.1 C14.1 C15.1 C16.1 J4.3 L1.2 NT1.2 TP4.1 TP6.1 | length 2118.5
  Signal Layer 2 w10: J4.3 650,115 672.71,92.29 1582.29,92.29 1605,115 1605,289 1591,303 ; NT1.2 1105,343.83 1166.83,282 1567.8,282 1580,294.2 ; 1978,1091 2069,1091 TP4.1
  Bottom Layer w40: TP6.1@1881,704 C16.1
  other v1: 1599,322 1599,359 1599,394 1599,445 1599,482 1599,517 1596,888 1596,925 1596,960 1596,1025 1596,1062 1596,1097
pads on no net: FID1.1 FID2.1 FID3.1 FID4.1 FID5.1 FID6.1 SH-J1.0 SH-J2.0

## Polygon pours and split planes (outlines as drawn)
GND on Top Layer "TOP_LAYER_GND_P106" (solid, pour order 106): 23,2482 24,2483 2500,2483 2500,16 17,16 17,2479 21,2483
VINS on Top Layer "TOP_LAYER_VINS_P094" (solid, pour order 94): 360,1647.5 1602,1647.5 1602,1480 360,1480
VINS on Top Layer "TOP_LAYER_VINS_P044" (solid, remove dead copper, pour order 44): 422,1479 422,1844 265,1844 265,1479
VIN on Top Layer "TOP_LAYER_VIN_P010" (solid, remove dead copper, pour order 10): 258.77,2178.5 258.77,1896 423.77,1896 423.77,2178.5
VINS on Top Layer "TOP_LAYER_VINS_P084" (solid, pour order 84): 1318,980 1308,990 1254,990 1254,771.32 1318,771.32
SW1 on Top Layer "TOP_LAYER_SW1_P082" (solid, pour order 82): 1360,710.5 1409.43,812 1409.43,597 1360,690.5 1361,710.5
GND on Signal Layer 2 "SIGNAL_LAYER_2_GND_P097" (solid, pour order 97): 28,2479 2500,2479 2500,25.49 29.04,25.49 28,26.53
VINS on Signal Layer 2 "SIGNAL_LAYER_2_VINS_P095" (solid, pour order 95): 1243,1388 1224,1388 1316,1388 1316,1296.78 1323,1289.78 1323,395 1243,395 1243,1353.27 1243,1374
GND on Signal Layer 1 "SIGNAL_LAYER_1_GND_P096" (solid, pour order 96): 28,2479 2500,2479 2500,25.49 25.49,25.49 28,28
GND on Bottom Layer "BOTTOM_LAYER_GND_P098" (solid, pour order 98): 28,2479 2420,2479 2500,2479 2500,25.49 25.49,25.49 25.49,2484.51

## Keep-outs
Keep-Out Layer:
  text ".Layer_Name" at 444.27,-1053.49 h60

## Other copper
Top Layer:
  rectangle net FB: 1170.24,653 1215.81,680
  rectangle net VCC: 1145,721 1211.72,747
  rectangle net VINS: 1254,1307 1367,1585
  rectangle net VOUT: 1507,287 1628,1113.15
  rectangle net VINS: 1258,492.41 1311,630
  rectangle net VINS: 1273.44,914.68 1304.44,980.68
  text ".Layer_Name" at 444.27,-1053.49 h60
Signal Layer 2:
  rectangle net VINS: 1242,1255 1385,1402
  rectangle net VOUT: 1565,264 1994,1114
Bottom Layer:
  text ".Layer_Name" at 444.27,-1053.49 h60

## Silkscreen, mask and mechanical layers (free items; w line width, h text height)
Top Overlay:
  lines w15: 1320.82,751.2 1321.02,751
  text "BSR107A" at 1527.64,2044 h60
  text "LM60440AQEVM" at 1525.46,1959 h60
  text "VCC" at 389,59 h60
  text "GND" at 797,59 h60
  text "VDIV" at 1014,58 h60
  text "VOUT" at 587,55 h60
  text ".Layer_Name" at 444.27,-1053.49 h60
Bottom Overlay:
  text ".Layer_Name" at 444.27,-1053.49 h60
Top Paste:
  text ".Layer_Name" at 444.27,-1053.49 h60
Bottom Paste:
  text ".Layer_Name" at 444.27,-1053.49 h60
Top Solder:
  rectangle: 1335,693 1398,707
  text ".Layer_Name" at 444.27,-1053.49 h60
  text ".Layer_Name" at 444.27,-1053.49 h60
Bottom Solder:
  text ".Layer_Name" at 444.27,-1053.49 h60
Drill Guide:
  text ".Layer_Name" at 444.27,-1053.49 h60
M1 Board Outline:
  the board outline again, w10
  text ".Layer_Name" at 444.27,-1053.49 h60
M2 Board Dimensions:
  rectangle: -7.73,-595 367.27,-470
  rectangle: -132.73,-470 -7.73,-345
  lines w7: -132.73,-470 867.27,-470 ; -7.73,-595 -7.73,-345 ; 117.27,-595 117.27,-345 ; 367.27,-595 367.27,-345 ; 617.27,-595 617.27,-345 ; -132.73,-595 -132.73,-345 867.27,-345 867.27,-595 -132.73,-595
  text ".Layer_Name" at 444.27,-1053.49 h60
M3 3D STEP Top:
  text ".Layer_Name" at 444.27,-1053.49 h60
M4 3D STEP Bottom:
  text ".Layer_Name" at 444.27,-1053.49 h60
M5 Assembly Top:
  lines w10: -424.73,-1125.17 6175.27,-1125.17 ; -424.73,-921.83 6177.27,-921.83 ; -424.73,-718.5 -424.73,-1328.5 3580.27,-1328.5 6177.27,-1328.5 6177.27,-718.5 -424.23,-718.5 -424.23,-1328.5 1151.27,-1328.5 ; 2040.27,-1328.5 2040.27,-718.5 ; 4769.27,-1335 4769.27,-1132.17
  text "COMPONENTS MARKED 'DNP' SHOULD NOT BE POPULATED." at 1020.77,-513.5 h60
  text "ASSEMBLY VARIANT:" at 1020.27,-629 h60
  text ".VariantName" at 2056.27,-629 h60
  text "PCB VIEWED FROM TOP SIDE" at -361.23,-850.67 h60
  text "BOARD #:" at 2115.27,-850.67 h60
  text ".PRJ_Number" at 2660.77,-850.67 h60
  text "TID #:" at 2115.27,-1054 h60
  text ".TID" at 2660.77,-1054 h60
  text "PLOT NAME =" at -361.23,-1259.34 h60
  text ".plot_File_Name" at 444.27,-1259.34 h60
  text "GENERATED    :" at 2117.27,-1259.34 h60
  text ".Print_Date" at 2986.77,-1259.34 h60
  text ".Print_Time" at 3715.77,-1259.34 h60
  text "TEXAS INSTRUMENTS" at 4980.27,-1259.34 h60
M6 Assembly Bottom:
  lines w10: -425.23,-922.33 6176.77,-922.33 ; -423.23,-1125.67 6176.77,-1125.67 ; 982.77,-1335.5 982.77,-1132.67 ; 1604.77,-922.33 1604.77,-719 ; 2444.77,-922.33 2444.77,-719 ; 3711.77,-1329 3711.77,-719 ; 4600.77,-1329 6176.27,-1329 6176.27,-719 -425.23,-719 -425.23,-1329 2171.77,-1329 6176.77,-1329 6176.77,-719
  text "COMPONENTS MARKED 'DNP' SHOULD NOT BE POPULATED." at 5969.27,-513 h60
  text ".VersionControl_RevNumber" at 902.77,-851.17 h60
  text "SVN REV:" at 1408.77,-851.17 h60
  text ".PCB_Rev" at 1955.27,-851.17 h60
  text "REV:" at 2246.77,-851.17 h60
  text ".PRJ_Number" at 3091.27,-851.17 h60
  text "BOARD #:" at 3636.77,-851.17 h60
  text ".TID" at 3091.27,-1054.5 h60
  text "TID #:" at 3636.77,-1054.5 h60
  text "TEXAS INSTRUMENTS" at 771.77,-1259.84 h60
  text ".Print_Time" at 2036.27,-1259.84 h60
  text ".Print_Date" at 2765.27,-1259.84 h60
  text "GENERATED    :" at 3634.77,-1259.84 h60
  text ".plot_File_Name" at 5307.77,-1259.84 h60
  text "PLOT NAME =" at 6113.27,-1259.84 h60
M9 Title Sheet:
  drawing of 57 lines, arcs and shapes, not listed
  text "1" at 607.11,7841.5 h70
  text "2" at 3102.77,7841.5 h70
  text "3" at 5592.12,7841.5 h70
  text "4" at 8098.78,7841.5 h70
  text "5" at 10597.77,7841.5 h70
  text "6" at 13102.77,7841.5 h70
  text "A" at -549.23,6698.5 h70
  text "A" at 14250.77,6698.5 h70
  text "B" at -549.23,4318.5 h70
  text "B" at 14250.77,4318.5 h70
  text "C" at -549.23,1943.5 h70
  text "C" at 14250.77,1943.5 h70
  text "PROJECT TITLE:" at 11210.77,82.5 h45
  text ".PRJ_Title" at 11260.77,-50.83 h70
  text "DESIGNED FOR:" at 11210.77,-218.5 h45
  text ".PRJ_Customer" at 11260.77,-358.5 h70
  text "D" at -549.23,-426.5 h70
  text "D" at 14250.77,-426.5 h70
  text "FILE NAME:" at 11210.77,-518.5 h45
  text ".PCB_File_Name_No_Path" at 11260.77,-638.5 h70
  text "Texas Instruments (TI) and/or its licensors do not warrant the accuracy or completeness of this specification" at 6241.27,-800.34 h45
  text "ENGINEER:" at 11210.77,-808.5 h45
  text "LAYOUT BY:" at 12715.77,-808.5 h45
  text "or any information contained therein. TI and/or its licensors do not warrant that this design will meet" at 6196.29,-913 h45
  text ".PRJ_Engineer" at 11260.77,-963.49 h70
  text ".PCB_Layout" at 12766.27,-963.49 h70
  text "the specifications, will be suitable for your application or fit for any particular purpose, or will operate in" at 6196.29,-1025.67 h45
  text ".Layer_Name" at 444.27,-1053.49 h60
  text "ALTIUM DESIGNER VERSION:" at 12715.77,-1118.5 h45
  text "an implementation. TI and/or its licensors do not warrant that the design is production worthy. You should" at 6196.29,-1138.33 h45
  text "completely validate and test your design implementation to confirm the system functionality for your application." at 6241.27,-1251 h45
  text ".print_Scale" at 11260.77,-1251.83 h70
  text ".Application_BuildNumber" at 12766.27,-1251.83 h70
  text "1" at 607.11,-1458.5 h70
  text "2" at 3102.77,-1458.5 h70
  text "3" at 5592.12,-1458.5 h70
  text "4" at 8098.78,-1458.5 h70
  text "5" at 10597.77,-1458.5 h70
  text "6" at 13102.77,-1458.5 h70
M10 Fab Notes:
  drawing of 484 lines, arcs and shapes, not listed
  text "DESIGN INFORMATION" at 12249.29,6161.17 h60
  text "MIN. TRACK WIDTH:" at 11604.73,6029.05 h60
  text "8" at 12700.97,6029.05 h60
  text "MIL" at 12855.73,6029.05 h60
  text "7.795" at 12561,5912 h60
  text "MIN. CLEARANCE:" at 11604.73,5904.92 h60
  text "MIL" at 12855.73,5904.92 h60
  text "MIN. VIA PAD SIZE:" at 11604.73,5780.8 h60
  text "16" at 12670.98,5780.8 h60
  text "MIL" at 12855.73,5780.8 h60
  text "0.05mm (2MIL)" at 12299.73,5650.9 h60
  text "MINIMUM ANNULAR RING" at 11275.5,5642.67 h60
  text "EXTERNAL" at 13007.73,5642.67 h60
  text "PER" at 11475.5,5532.55 h60
  text "IPC-D-275 CLASS 2 LEVEL C" at 11695.5,5532.54 h60
  text "MIL, HOLES" at 13183.73,5432.07 h60
  text "+/-" at 12791.27,5423.48 h60
  text "+/-" at 13645.27,5423.48 h60
  text "REGISTRATION TOLERANCES:" at 11275.5,5422.42 h60
  text "METAL" at 12475.27,5422.42 h60
  text "5" at 13051.47,5422.42 h60
  text "3" at 13884.47,5422.42 h60
  text "MIL" at 14000.73,5422.42 h60
  text "HOLE SIZE TOLERANCE (UNLESS OTHERWISE SPECIFIED):" at 11275.5,5324.1 h60
  text "+/-" at 13645.27,5321.23 h60
  text "3" at 13884.47,5320.17 h60
  text "MIL" at 14000.73,5320.17 h60
  text "MATERIAL:" at 11200.73,5182.52 h60
  text "FR-4 High Tg" at 12187.18,5054 h60
  text "X" at 12042.74,5046.01 h60
  text "FR-408" at 11621.73,5041.49 h60
  text "OTHER" at 13109.73,5041.49 h60
  text "65.2 MIL (1.6mm) +/-10%" at 11941.83,4898.46 h60
  text "X" at 11821.74,4896.01 h60
  text "THICKNESS:" at 11275.5,4890.24 h60
  text "OTHER" at 13226.73,4890.24 h60
  text "TOLERANCE:" at 11275.5,4751.92 h60
  text "X" at 12123.74,4751.92 h60
  text "ANSI IPC-6012 TYPE 3 CLASS 2" at 12301.75,4751.92 h60
  text "OTHER +/-" at 12301.73,4607.73 h60
  text "BOW & TWIST:" at 11275.5,4462.54 h60
  text "X" at 12123.74,4462.54 h60
  text "ANSI IPC-6012 TYPE 3 CLASS 2" at 12301.75,4462.54 h60
  text "OTHER +/-" at 12301.73,4315.85 h60
  text "DRILLING:" at 11200.73,4185.23 h60
  text "NC_DRILL FILES" at 12961.73,4080.04 h60
  text "REFERENCE:" at 11275.5,4076.1 h60
  text "X" at 11932.74,4076.01 h60
  text "AS SHOWN" at 12110.73,4076.1 h60
  text "X" at 12833.74,4076.1 h60
  text "OTHER" at 13259.73,3933.85 h60
  text "PTH COPPER THICKNESS:" at 11275.18,3930.32 h60
  text "X" at 12414.41,3930.32 h60
  text "20-30 um" at 12542.41,3930.32 h60
  text "BOARD FINISH:" at 11200.73,3782.73 h60
  text "SILKSCREEN:" at 11355.95,3672.6 h60
  text "X" at 12313.74,3672.6 h60
  text "TOP" at 12430.73,3672.6 h60
  text "X" at 12823.74,3672.6 h60
  text "BOTTOM" at 12941.73,3672.6 h60
  text "SILKSCREEN COLOR:" at 11355.95,3517.41 h60
  text "X" at 12312.74,3517.41 h60
  text "WHITE" at 12430.73,3517.41 h60
  text "OTHER" at 12941.73,3517.41 h60
  text "X" at 12443.74,3373.96 h60
  text "GREEN" at 12561.73,3373.96 h60
  text "OTHER" at 13179.73,3373.96 h60
  text "SOLDER RESIST COLOR:" at 11355.95,3367.1 h60
  text "X" at 12443.74,3219.71 h60
  text "MATTE" at 12561.73,3219.71 h60
  text "SEMI-GLOSS" at 13179.27,3219.07 h60
  text "IMMERSION GOLD (ENIG)" at 12261.73,3046.94 h60
  text "ENEPIG" at 13599.27,3039.72 h60
  text "SURFACE FINISH:" at 11200.73,3038.72 h60
  text "X" at 12083.74,3038.72 h60
  text "IMM. TIN/SILVER OR EQUIV" at 11530.27,2901.4 h60
  text "OTHER" at 12961.73,2897.47 h60
  text "ARRAY/PANEL:" at 11200.73,2742.09 h60
  text "X" at 12080,2735 h60
  text "CUT AND TRIM PER M1 BOARD OUTLINE" at 12261.73,2733.87 h60
  text "N.C. ROUTE" at 12261.73,2597.9 h60
  text "V. SCORE" at 13127.73,2597.9 h60
  text "CERTIFICATION:" at 11200.73,2468.77 h60
  text "MATERIALS AND WORKMANSHIP FOR ALL PCBS" at 11925.73,2468.77 h60
  text "TO MEET OR EXCEED THE REQUIREMENTS OF:" at 11925.73,2374.71 h60
  text "Layer" at 3631.74,2339 h60
  text "Name" at 4041.66,2339 h60
  text "Material" at 4981.4,2339 h60
  text "Thickness" at 5841.16,2339 h60
  text "Constant" at 6491,2339 h60
  text "Board Layer Stack" at 7060.86,2339 h60
  text "X" at 11563.24,2246.08 h60
  text "ANSI IPC-A-600F CLASS ->" at 11691.24,2246.08 h60
  text "X" at 13339.24,2246.08 h60
  text "2" at 13449.24,2246.08 h60
  text "1" at 13134.24,2244.58 h60
  text "3" at 13803.24,2244.58 h60
  text "1" at 3631.74,2219 h60
  text "Top Overlay" at 4041.66,2219 h60
  text "2" at 3631.74,2099 h60
  text "Top Solder" at 4041.66,2099 h60
  text "Solder Resist" at 4981.4,2099 h60
  text "0.40mil" at 5841.16,2099 h60
  text "3.5" at 6491,2099 h60
  text "X" at 12375.24,2098.39 h60
  text "RoHS" at 12503.24,2098.39 h60
  text "OTHER" at 13147.64,2098.39 h60
  text "PER ORDER" at 13544.69,2098.39 h60
  text "3" at 3631.74,1979 h60
  text "Top Layer" at 4041.66,1979 h60
  text "Copper" at 4981.4,1979 h60
  text "2.80mil" at 5841.16,1979 h60
  text "ALL BOARDS MUST MEET OR EXCEED UL94-V0 REQUIREMENTS." at 11228.27,1944.57 h60
  text "4" at 3631.74,1859 h60
  text "Dielectric 3" at 4041.66,1859 h60
  text "FR-4 High TG" at 4981.4,1859 h60
  text "14.00mil" at 5841.16,1859 h60
  text "4.2" at 6491,1859 h60
  text "PCB MUST BEAR THE UL94V-0 UL REGISTERED MATERIAL ID NUMBER" at 11228.27,1828.5 h60
  text "5" at 3631.74,1739 h60
  text "Signal Layer 1" at 4041.66,1739 h60
  text "Copper" at 4981.4,1739 h60
  text "1.40mil" at 5841.16,1739 h60
  text "ADDITIONAL REQUIREMENTS:" at 11200.73,1659.08 h60
  text "6" at 3631.74,1619 h60
  text "Dielectric 2" at 4041.66,1619 h60
  text "FR-4 High TG" at 4981.4,1619 h60
  text "28.00mil" at 5841.16,1619 h60
  text "4.2" at 6491,1619 h60
  text "MICROSECTION:" at 11275.5,1551.95 h60
  text "YES" at 12181.24,1551.95 h60
  text "7" at 3631.74,1499 h60
  text "Signal Layer 2" at 4041.66,1499 h60
  text "Copper" at 4981.4,1499 h60
  text "1.40mil" at 5841.16,1499 h60
  text "REQUIRED" at 13042.73,1407.62 h60
  text "BARE BOARD ELEC. TEST:" at 11275.5,1404.76 h60
  text "NONE" at 12581.24,1404.76 h60
  text "X" at 12924.74,1404.76 h60
  text "PER ORDER" at 13634.73,1404.76 h60
  text "8" at 3631.74,1379 h60
  text "Dielectric1" at 4041.66,1379 h60
  text "FR-4 HIgh TG" at 4981.4,1379 h60
  text "14.00mil" at 5841.16,1379 h60
  text "4.2" at 6491,1379 h60
  text "9" at 3631.74,1259 h60
  text "Bottom Layer" at 4041.66,1259 h60
  text "Copper" at 4981.4,1259 h60
  text "2.80mil" at 5841.16,1259 h60
  text "XX MIL VIAS REQUIRE NON-CONDUCTIVE FILL AND PLANARIZE" at 11443.65,1199.82 h59
  text "10" at 3631.74,1139 h60
  text "Bottom Solder" at 4041.66,1139 h60
  text "Solder Resist" at 4981.4,1139 h60
  text "0.40mil" at 5841.16,1139 h60
  text "3.5" at 6491,1139 h60
  text "XX MIL VIAS REQUIRE CONDUCTIVE FILL AND PLANARIZE" at 11451.65,1095.84 h60
  text "11" at 3631.74,1019 h60
  text "Bottom Overlay" at 4041.66,1019 h60
  text "OUTER XX MIL VIAS REQUIRE 50 OHM SINGLE-ENDED IMPEDANCE" at 11450.67,932.46 h58
  text "LAYER 2 & 3 (INNER LAYERS) XX MIL WIDE, XX MIL SPACE / TRACES REQUIRE 100 OHM DIFFERENTIAL IMPEDANCE" at 11442.67,696.74 h60
  text ".Layer_Name" at 444.27,-1053.49 h60
M11 Gerber Information:
  lines w10: -424.73,-1125.17 6175.27,-1125.17 ; -424.73,-921.83 6177.27,-921.83 ; -424.73,-718.5 -424.73,-1328.5 3580.27,-1328.5 6177.27,-1328.5 6177.27,-718.5 -424.23,-718.5 -424.23,-1328.5 1151.27,-1328.5 ; 2040.27,-1328.5 2040.27,-718.5 ; 4769.27,-1335 4769.27,-1132.17
  text "ALL ARTWORK VIEWED FROM TOP SIDE" at -361.23,-850.67 h60
  text "BOARD #:" at 2115.27,-850.67 h60
  text ".PRJ_Number" at 2660.77,-850.67 h60
  text "LAYER NAME =" at -361.23,-1053.49 h60
  text "TID #:" at 2115.27,-1054 h60
  text ".TID" at 2660.77,-1054 h60
  text "PLOT NAME =" at -361.23,-1259.34 h60
  text ".plot_File_Name" at 444.27,-1259.34 h60
  text "GENERATED    :" at 2117.27,-1259.34 h60
  text ".Print_Date" at 2986.77,-1259.34 h60
  text ".Print_Time" at 3715.77,-1259.34 h60
  text "TEXAS INSTRUMENTS" at 4980.27,-1259.34 h60
M12 Stackup:
  text ".Layer_Name" at 444.27,-1053.49 h60
M13 Component Bodies Top:
  text ".Layer_Name" at 444.27,-1053.49 h60
M14 Component Bodies Bottom:
  text ".Layer_Name" at 444.27,-1053.49 h60
M15 Courtyards Top:
  text ".Layer_Name" at 444.27,-1053.49 h60
M16 Courtyards Bottom:
  text ".Layer_Name" at 444.27,-1053.49 h60
Drill Drawing:
  circle w10: c5230.99,3042.96 r27.63
  lines w10: 5203.36,2780.51 5217.18,2780.51 5230.99,2766.7 5244.8,2780.51 5258.62,2780.51 5244.8,2794.32 5258.62,2808.14 5244.8,2808.14 5230.99,2821.95 5217.18,2808.14 5203.36,2808.14 5217.18,2794.32 5203.36,2780.51 ; 5203.36,2891.02 5258.62,2891.02 5258.62,2946.27 5203.36,2946.27 5203.36,2891.02 ; 5203.36,3139.66 5230.99,3153.47 5258.62,3139.66 5244.8,3167.28 5258.62,3194.91 5230.99,3181.1 5203.36,3194.91 5217.18,3167.28 5203.36,3139.66
  lines w12: 5153.27,2729.4 8384.76,2729.4 ; 5153.27,3226.68 8384.76,3226.68 ; 5491.13,2605.08 5491.13,3351 ; 5823.14,2605.08 5823.14,3351 ; 6459.7,2605.08 6459.7,3351 ; 6718.84,2605.08 6718.84,3351 ; 7094,2605.08 7094,3351 ; 7818.33,2605.08 7818.33,3351 ; 5153.27,2605.08 8384.76,2605.08 8384.76,3351 5153.27,3351 5153.27,2605.08
  text "Symbol" at 5227.86,3263.98 h72
  text "Quantity" at 5528.43,3263.98 h72
  text "Finished Hole Size" at 5860.43,3263.98 h72
  text "Plated" at 6496.99,3263.98 h72
  text "Hole Type" at 6756.13,3263.98 h72
  text "Drill Layer Pair" at 7131.29,3263.98 h72
  text "Hole Tolerance" at 7855.62,3263.98 h72
  text "265" at 5528.43,3139.66 h60
  text "8.00mil (0.203mm)" at 5860.43,3139.66 h60
  text "PTH" at 6496.99,3139.66 h60
  text "Round" at 6756.13,3139.66 h60
  text "Top Layer - Bottom Layer" at 7131.29,3139.66 h60
  text "6" at 5528.43,3015.34 h60
  text "40.00mil (1.016mm)" at 5860.43,3015.34 h60
  text "PTH" at 6496.99,3015.34 h60
  text "Round" at 6756.13,3015.34 h60
  text "Top Layer - Bottom Layer" at 7131.29,3015.34 h60
  text "8" at 5528.43,2891.02 h60
  text "63.00mil (1.600mm)" at 5860.43,2891.02 h60
  text "PTH" at 6496.99,2891.02 h60
  text "Round" at 6756.13,2891.02 h60
  text "Top Layer - Bottom Layer" at 7131.29,2891.02 h60
  text "2" at 5528.43,2766.7 h60
  text "122.05mil (3.100mm)" at 5860.43,2766.7 h60
  text "PTH" at 6496.99,2766.7 h60
  text "Round" at 6756.13,2766.7 h60
  text "Top Layer - Bottom Layer" at 7131.29,2766.7 h60
  text "281 Total" at 5528.43,2642.38 h60
  text ".Layer_Name" at 444.27,-1053.49 h60
M17 Embedded Cavity:
  text ".Layer_Name" at 444.27,-1053.49 h60
M18 Embedded Assembly:
  text ".Layer_Name" at 444.27,-1053.49 h60
M19 Embedded Keepout:
  text ".Layer_Name" at 444.27,-1053.49 h60

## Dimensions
0,0 to 2500,0 on M2 Board Dimensions
0,0 to 0,2500 on M2 Board Dimensions
-132.73,-595 to 867.27,-595 on M2 Board Dimensions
